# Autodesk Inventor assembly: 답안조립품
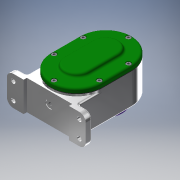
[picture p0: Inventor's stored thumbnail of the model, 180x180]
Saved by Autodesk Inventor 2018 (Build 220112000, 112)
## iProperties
Created: 2021-05
Part Number: 답안조립품
Material: 일반
Document SubType Name: Assembly
Designer: Admin
Author: Admin
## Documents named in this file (19)
- C:\Users\Admin\Desktop\710509V1015\답안조립품.iam
- C:\Users\Admin\Desktop\710509V1015\본체.ipt
- C:\Users\Admin\Desktop\710509V1015\축 A.ipt
- C:\Users\Admin\Desktop\710509V1015\베어링 6001.ipt
- 베어링 6001.ipt
- C:\Users\Admin\Desktop\710509V1015\베어링 6002.ipt
- 베어링 6002.ipt
- C:\Users\Admin\Desktop\710509V1015\칼라.ipt
- C:\Users\Admin\Desktop\710509V1015\키 5 x 5 x 12.ipt
- C:\Users\Admin\Desktop\710509V1015\스퍼기어 A.ipt
- C:\Users\Admin\Desktop\710509V1015\축 B.ipt
- C:\Users\Admin\Desktop\710509V1015\키 4 x 4 x 12.ipt
- C:\Users\Admin\Desktop\710509V1015\스퍼기어 B.ipt
- C:\Users\Admin\Desktop\710509V1015\개스킷 A.ipt
- C:\Users\Admin\Desktop\710509V1015\개스킷 B.ipt
- C:\Users\Admin\Desktop\710509V1015\커버 A.ipt
- C:\Users\Admin\Desktop\710509V1015\커버 B.ipt
- C:\Users\Admin\Desktop\710509V1015\볼트 M4.ipt
- C:\Users\Admin\Desktop\710509V1015\오일 실 12 22 7.ipt
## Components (2 placed, 2 different names)
1. 개스킷 A:1
2. 개스킷 B:1
